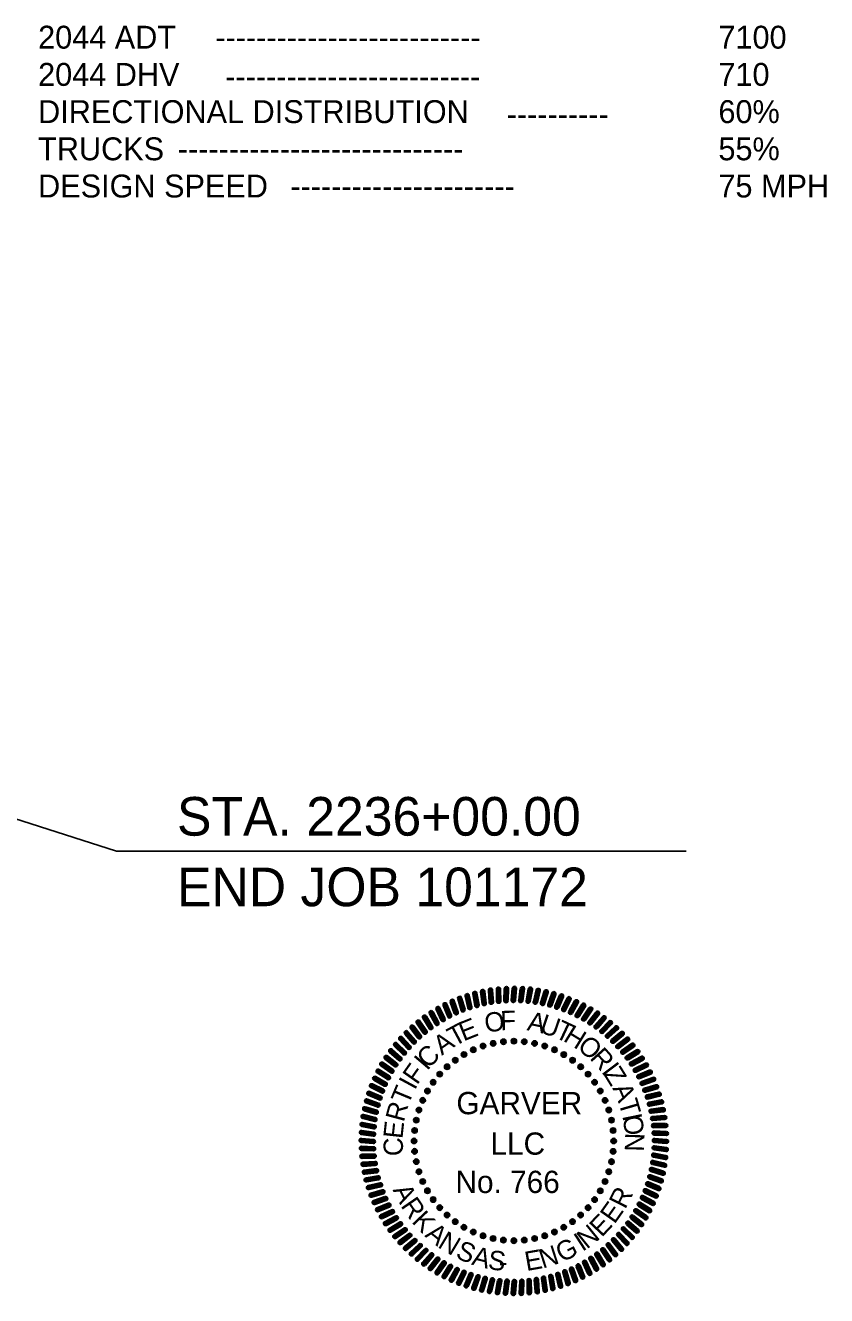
# Model space of a CAD drawing. Extents: x 1164457 to 1439835, y 1590918 to 1773502.
# Drawn here: x 1368755 to 1424710, y 1592326 to 1681073 of the extents above; entities that cross this region are included whole.
import ezdxf

# ---------------------------------------------------------------- set-up
doc = ezdxf.new("R2010")
doc.units = 0
for name, color, linetype in [('G-ANNO-STMP', 7, 'Continuous'), ('G-ANNO-TEXT', 7, 'Continuous'), ('R_Draft', 7, 'Continuous')]:
    doc.layers.add(name, color=color, linetype=linetype)

# ---------------------------------------------------------------- blocks, each defined once
blk = doc.blocks.new('SEALDO')
at = {"layer": 'G-ANNO-TEXT'}
for radius in [0.0396, 0.0305, 0.0213, 0.0122, 0.00305]:
    blk.add_circle((1.403, -0.456), radius, dxfattribs=at)
blk = doc.blocks.new('SEALRI')
at = {"layer": 'G-ANNO-TEXT'}
for p, q in [((-0.023, 2.258), (-0.038, 2.081)), ((-0.008, 2.281), (-0.028, 2.056)), ((0.004, 2.286), (-0.016, 2.049)), ((0.016, 2.285), (-0.004, 2.048)), ((0.028, 2.278), (0.008, 2.052)), ((0.023, 2.076), (0.038, 2.253))]:
    blk.add_line(p, q, dxfattribs=at)
for centre, start, end in [((0.008, 2.256), 355, 175), ((-0.008, 2.078), 175, 355)]:
    blk.add_arc(centre, 0.0305, start, end, dxfattribs=at)

msp = doc.modelspace()

# ---------------------------------------------------------------- linework, layer by layer
at = {"layer": 'R_Draft'}
for p, q in [((1375114, 1623387), (1297809, 1647974)), ((1414895, 1623387), (1375114, 1623387))]:
    msp.add_line(p, q, dxfattribs=at)

# ---------------------------------------------------------------- block references
at = {"layer": 'G-ANNO-STMP'}
for name, xscale, yscale, rotation in [('SEALRI', 4724.3165369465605, 4724.3165369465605, 18), ('SEALRI', 4724.31653694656, 4724.3165369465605, 15.000000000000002), ('SEALRI', 4724.31653694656, 4724.316536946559, 12.000000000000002), ('SEALRI', 4724.31653694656, 4724.31653694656, 9), ('SEALRI', 4724.316536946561, 4724.316536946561, 5.999999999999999), ('SEALRI', 4724.316536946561, 4724.3165369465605, 3), ('SEALRI', 4724.316536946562, 4724.316536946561, -2.9999999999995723), ('SEALRI', 4724.3165369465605, 4724.316536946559, -5.9999999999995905), ('SEALRI', 4724.316536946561, 4724.316536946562, -8.999999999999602), ('SEALRI', 4724.31653694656, 4724.316536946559, -11.999999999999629), ('SEALRI', 4724.3165369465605, 4724.316536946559, -14.999999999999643), ('SEALRI', 4724.3165369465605, 4724.316536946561, -17.99999999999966), ('SEALRI', 4724.3165369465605, 4724.316536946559, 30.000000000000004), ('SEALRI', 4724.316536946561, 4724.31653694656, 26.99999999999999), ('SEALRI', 4724.3165369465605, 4724.316536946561, 23.99999999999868), ('SEALRI', 4724.3165369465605, 4724.31653694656, 20.999999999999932), ('SEALRI', 4724.3165369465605, 4724.3165369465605, -20.99999999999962), ('SEALRI', 4724.3165369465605, 4724.31653694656, -23.999999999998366), ('SEALRI', 4724.316536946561, 4724.316536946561, -26.999999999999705), ('SEALRI', 4724.3165369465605, 4724.31653694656, -29.99999999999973), ('SEALRI', 4724.31653694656, 4724.31653694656, 36.00000000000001), ('SEALRI', 4724.3165369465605, 4724.31653694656, 33), ('SEALRI', 4724.3165369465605, 4724.3165369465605, -32.999999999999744), ('SEALRI', 4724.3165369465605, 4724.316536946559, -35.999999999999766), ('SEALRI', 4724.3165369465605, 4724.316536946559, 44.999999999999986), ('SEALRI', 4724.3165369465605, 4724.316536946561, 41.999999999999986), ('SEALRI', 4724.3165369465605, 4724.316536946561, 38.999999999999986), ('SEALRI', 4724.3165369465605, 4724.316536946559, -38.999999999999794), ('SEALRI', 4724.31653694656, 4724.3165369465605, -41.99999999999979), ('SEALRI', 4724.3165369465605, 4724.3165369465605, -44.999999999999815), ('SEALRI', 4724.3165369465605, 4724.3165369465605, 50.99999999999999), ('SEALRI', 4724.316536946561, 4724.316536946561, 47.99999999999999), ('SEALDO', 4724.316536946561, 4724.316536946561, 125.99999999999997), ('SEALDO', 4724.31653694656, 4724.31653694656, 119.99999999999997), ('SEALDO', 4724.31653694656, 4724.316536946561, 113.99999999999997), ('SEALDO', 4724.3165369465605, 4724.3165369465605, 107.99999999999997), ('SEALDO', 4724.31653694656, 4724.3165369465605, 101.99999999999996), ('SEALDO', 4724.316536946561, 4724.316536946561, 95.99999999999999), ('SEALDO', 4724.3165369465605, 4724.3165369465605, 90), ('SEALRI', 4724.3165369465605, 4724.316536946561, -47.99999999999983), ('SEALRI', 4724.3165369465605, 4724.316536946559, -50.999999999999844), ('SEALRI', 4724.3165369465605, 4724.31653694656, 56.99999999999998), ('SEALRI', 4724.31653694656, 4724.31653694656, 54), ('SEALDO', 4724.31653694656, 4724.31653694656, 144), ('SEALDO', 4724.3165369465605, 4724.316536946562, 138), ('SEALDO', 4724.31653694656, 4724.316536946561, 131.99999999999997), ('SEALDO', 4724.316536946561, 4724.316536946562, 83.99999999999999), ('SEALDO', 4724.31653694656, 4724.31653694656, 77.99999999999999), ('SEALDO', 4724.3165369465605, 4724.3165369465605, 72), ('SEALRI', 4724.3165369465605, 4724.31653694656, -53.99999999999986), ('SEALRI', 4724.316536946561, 4724.316536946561, -56.999999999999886), ('SEALRI', 4724.31653694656, 4724.316536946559, 63), ('SEALRI', 4724.31653694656, 4724.31653694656, 59.999999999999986), ('SEALDO', 4724.3165369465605, 4724.31653694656, 150), ('SEALDO', 4724.3165369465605, 4724.316536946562, 66.00000000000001), ('SEALRI', 4724.31653694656, 4724.3165369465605, -59.99999999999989), ('SEALRI', 4724.316536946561, 4724.316536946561, -62.99999999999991), ('SEALRI', 4724.3165369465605, 4724.316536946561, 65.99999999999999), ('SEALDO', 4724.31653694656, 4724.31653694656, 162.00000000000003), ('SEALDO', 4724.3165369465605, 4724.316536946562, 156.00000000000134), ('SEALDO', 4724.3165369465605, 4724.31653694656, 60.00000000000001), ('SEALDO', 4724.31653694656, 4724.31653694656, 54), ('SEALRI', 4724.3165369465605, 4724.316536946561, -65.99999999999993), ('SEALRI', 4724.3165369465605, 4724.3165369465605, 72), ('SEALRI', 4724.316536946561, 4724.316536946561, 68.99999999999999), ('SEALDO', 4724.316536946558, 4724.3165369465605, 168.00000000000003), ('SEALDO', 4724.3165369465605, 4724.316536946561, 48.00000000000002), ('SEALRI', 4724.3165369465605, 4724.3165369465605, -68.99999999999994), ('SEALRI', 4724.3165369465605, 4724.3165369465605, -71.99999999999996), ('SEALRI', 4724.31653694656, 4724.316536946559, 78.00000000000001), ('SEALRI', 4724.31653694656, 4724.31653694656, 75.00000000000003), ('SEALDO', 4724.3165369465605, 4724.3165369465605, -179.99999999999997), ('SEALDO', 4724.316536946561, 4724.3165369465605, 174.00000000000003), ('SEALDO', 4724.316536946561, 4724.316536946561, 42.000000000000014), ('SEALDO', 4724.31653694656, 4724.31653694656, 36.00000000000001), ('SEALRI', 4724.3165369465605, 4724.3165369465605, -74.99999999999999), ('SEALRI', 4724.31653694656, 4724.316536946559, -78), ('SEALRI', 4724.31653694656, 4724.3165369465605, 81), ('SEALDO', 4724.316536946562, 4724.316536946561, -173.99999999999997), ('SEALDO', 4724.3165369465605, 4724.31653694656, 29.999999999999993), ('SEALRI', 4724.31653694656, 4724.31653694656, -81.00000000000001), ('SEALRI', 4724.3165369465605, 4724.316536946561, 87.00000000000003), ('SEALRI', 4724.316536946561, 4724.316536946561, 84.00000000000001), ('SEALDO', 4724.31653694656, 4724.316536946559, -167.99999999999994), ('SEALDO', 4724.3165369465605, 4724.316536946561, 23.99999999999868), ('SEALRI', 4724.316536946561, 4724.316536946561, -84.00000000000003), ('SEALRI', 4724.3165369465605, 4724.316536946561, -87.00000000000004), ('SEALRI', 4724.3165369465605, 4724.3165369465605, 90.00000000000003), ('SEALRI', 4724.316536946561, 4724.3165369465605, 93), ('SEALDO', 4724.3165369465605, 4724.316536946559, -161.9999999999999), ('SEALDO', 4724.3165369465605, 4724.3165369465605, 18), ('SEALRI', 4724.316536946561, 4724.316536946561, -93.00000000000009), ('SEALRI', 4724.3165369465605, 4724.3165369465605, -90.00000000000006), ('SEALRI', 4724.316536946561, 4724.316536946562, 96.00000000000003), ('SEALDO', 4724.31653694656, 4724.31653694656, -156.00000000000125), ('SEALDO', 4724.3165369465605, 4724.3165369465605, -149.99999999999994), ('SEALDO', 4724.316536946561, 4724.316536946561, 5.999999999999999), ('SEALDO', 4724.31653694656, 4724.316536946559, 12.000000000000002), ('SEALRI', 4724.3165369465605, 4724.3165369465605, -96.0000000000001), ('SEALRI', 4724.3165369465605, 4724.3165369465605, 99.00000000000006), ('SEALRI', 4724.31653694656, 4724.316536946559, 102.00000000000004), ('SEALDO', 4724.316536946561, 4724.316536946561, -143.99999999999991), ('SEALRI', 4724.31653694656, 4724.316536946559, -102.00000000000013), ('SEALRI', 4724.3165369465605, 4724.3165369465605, -99.00000000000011), ('SEALRI', 4724.3165369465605, 4724.3165369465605, 105.00000000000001), ('SEALRI', 4724.3165369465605, 4724.3165369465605, 108.00000000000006), ('SEALDO', 4724.316536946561, 4724.316536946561, -137.9999999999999), ('SEALDO', 4724.31653694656, 4724.3165369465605, -6.000000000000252), ('SEALRI', 4724.3165369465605, 4724.31653694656, -108.00000000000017), ('SEALRI', 4724.316536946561, 4724.31653694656, -105.00000000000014), ('SEALRI', 4724.31653694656, 4724.3165369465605, 111.00000000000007), ('SEALRI', 4724.3165369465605, 4724.3165369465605, 114.00000000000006), ('SEALDO', 4724.3165369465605, 4724.3165369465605, -131.99999999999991), ('SEALDO', 4724.316536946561, 4724.31653694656, -125.9999999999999), ('SEALDO', 4724.3165369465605, 4724.3165369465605, -18.000000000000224), ('SEALDO', 4724.31653694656, 4724.31653694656, -12.000000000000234), ('SEALRI', 4724.3165369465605, 4724.316536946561, -114.0000000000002), ('SEALRI', 4724.3165369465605, 4724.3165369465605, -111.00000000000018), ('SEALRI', 4724.31653694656, 4724.3165369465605, 117.00000000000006), ('SEALRI', 4724.31653694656, 4724.31653694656, 120.00000000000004), ('SEALDO', 4724.3165369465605, 4724.3165369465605, -119.99999999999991), ('SEALDO', 4724.3165369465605, 4724.316536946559, -23.999999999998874), ('SEALRI', 4724.3165369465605, 4724.316536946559, -120.00000000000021), ('SEALRI', 4724.31653694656, 4724.316536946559, -117.00000000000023), ('SEALRI', 4724.31653694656, 4724.31653694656, 123.00000000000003), ('SEALRI', 4724.316536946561, 4724.31653694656, 126.00000000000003), ('SEALDO', 4724.316536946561, 4724.316536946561, -113.99999999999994), ('SEALDO', 4724.3165369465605, 4724.31653694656, -107.99999999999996), ('SEALDO', 4724.3165369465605, 4724.3165369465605, -36.00000000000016), ('SEALDO', 4724.31653694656, 4724.3165369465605, -30.00000000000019), ('SEALRI', 4724.3165369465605, 4724.3165369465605, -126.00000000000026), ('SEALRI', 4724.3165369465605, 4724.3165369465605, -123.00000000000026), ('SEALRI', 4724.3165369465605, 4724.3165369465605, 129.00000000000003), ('SEALRI', 4724.3165369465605, 4724.31653694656, 132), ('SEALDO', 4724.31653694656, 4724.316536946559, -101.99999999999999), ('SEALDO', 4724.316536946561, 4724.316536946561, -96), ('SEALDO', 4724.3165369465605, 4724.3165369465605, -90.00000000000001), ('SEALDO', 4724.3165369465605, 4724.3165369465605, -60.0000000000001), ('SEALDO', 4724.3165369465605, 4724.3165369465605, -54.000000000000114), ('SEALDO', 4724.3165369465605, 4724.3165369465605, -48.00000000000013), ('SEALDO', 4724.31653694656, 4724.31653694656, -42.00000000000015), ('SEALRI', 4724.31653694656, 4724.31653694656, -132.00000000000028), ('SEALRI', 4724.3165369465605, 4724.31653694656, -129.00000000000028), ('SEALRI', 4724.31653694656, 4724.316536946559, 135), ('SEALRI', 4724.3165369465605, 4724.316536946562, 138), ('SEALRI', 4724.31653694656, 4724.31653694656, 140.99999999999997), ('SEALDO', 4724.316536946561, 4724.316536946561, -84.00000000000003), ('SEALDO', 4724.31653694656, 4724.3165369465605, -78.00000000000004), ('SEALDO', 4724.3165369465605, 4724.316536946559, -72.00000000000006), ('SEALDO', 4724.3165369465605, 4724.3165369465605, -66.00000000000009), ('SEALRI', 4724.3165369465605, 4724.316536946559, -141.0000000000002), ('SEALRI', 4724.3165369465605, 4724.31653694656, -138.00000000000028), ('SEALRI', 4724.31653694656, 4724.31653694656, -135.00000000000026), ('SEALRI', 4724.31653694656, 4724.31653694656, 144), ('SEALRI', 4724.31653694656, 4724.3165369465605, 146.99999999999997), ('SEALRI', 4724.3165369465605, 4724.3165369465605, 149.99999999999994), ('SEALRI', 4724.3165369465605, 4724.3165369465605, -150.00000000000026), ('SEALRI', 4724.3165369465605, 4724.3165369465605, -147.00000000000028), ('SEALRI', 4724.31653694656, 4724.3165369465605, -144.00000000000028), ('SEALRI', 4724.3165369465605, 4724.3165369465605, 152.99999999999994), ('SEALRI', 4724.31653694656, 4724.316536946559, 156.00000000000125), ('SEALRI', 4724.3165369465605, 4724.3165369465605, 159), ('SEALRI', 4724.31653694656, 4724.31653694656, 161.99999999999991), ('SEALRI', 4724.31653694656, 4724.3165369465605, -162.00000000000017), ('SEALRI', 4724.3165369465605, 4724.3165369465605, -159.00000000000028), ('SEALRI', 4724.316536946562, 4724.316536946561, -156.00000000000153), ('SEALRI', 4724.31653694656, 4724.316536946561, -153.00000000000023), ('SEALRI', 4724.31653694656, 4724.3165369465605, 164.99999999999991), ('SEALRI', 4724.31653694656, 4724.316536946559, 167.99999999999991), ('SEALRI', 4724.3165369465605, 4724.3165369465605, 170.9999999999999), ('SEALRI', 4724.3165369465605, 4724.316536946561, 173.9999999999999), ('SEALRI', 4724.316536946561, 4724.316536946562, 176.9999999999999), ('SEALRI', 4724.3165369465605, 4724.3165369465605, 179.99999999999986), ('SEALRI', 4724.316536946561, 4724.316536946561, -177.00000000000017), ('SEALRI', 4724.3165369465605, 4724.31653694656, -174.00000000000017), ('SEALRI', 4724.3165369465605, 4724.3165369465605, -171.00000000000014), ('SEALRI', 4724.31653694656, 4724.3165369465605, -168.0000000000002), ('SEALRI', 4724.3165369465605, 4724.316536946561, -165.0000000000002)]:
    msp.add_blockref(name, (1402870, 1603133), dxfattribs=dict(at, xscale=xscale, yscale=yscale, rotation=rotation))
at = {"layer": 'G-ANNO-STMP', "xscale": 4724.3165369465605, "yscale": 4724.3165369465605}
for name in ['SEALRI', 'SEALDO']:
    msp.add_blockref(name, (1402870, 1603133), dxfattribs=at)

# ---------------------------------------------------------------- texts
at = {"layer": 'G-ANNO-STMP'}
for s, rotation, p in [('E', 21.61044, (1399351, 1610080)), ('O', 8.2771, (1400914, 1610689)), ('F', 1.61044, (1401938, 1610864)), ('A', 348.2771, (1403742, 1610876)), ('U', 341.27715, (1404586, 1610741)), ('T', 28.2771, (1398698, 1609699)), ('T', 334.94377, (1405647, 1610398)), ('H', 328.2771, (1406255, 1610158)), ('A', 34.94377, (1397840, 1609077)), ('O', 319.7874, (1407231, 1609604)), ('I', 49.74076, (1396814, 1607988)), ('C', 44.38813, (1396883, 1608126)), ('R', 311.99331, (1408116, 1608897)), ('F', 54.94377, (1396111, 1606999)), ('I', 307.00814, (1408940, 1607971)), ('Z', 301.61044, (1409099, 1607809)), ('I', 61.61044, (1395950, 1606634)), ('T', 67.43139, (1395497, 1605588)), ('A', 292.97516, (1409735, 1606828)), ('R', 74.94377, (1395181, 1604399)), ('T', 286.3085, (1410158, 1605851)), ('I', 281.61044, (1410429, 1604901)), ('O', 276.48226, (1410481, 1604853)), ('E', 83.89849, (1395084, 1603245)), ('C', 91.88416, (1395144, 1602092)), ('N', 268.2771, (1410650, 1603714)), ('A', 296.57465, (1394394, 1599713)), ('R', 304.61826, (1394927, 1598601)), ('R', 63.09594, (1410647, 1598312)), ('E', 54.73091, (1409896, 1597276)), ('K', 313.3805, (1395685, 1597472)), ('E', 46.68075, (1409002, 1596354)), ('A', 321.25836, (1396598, 1596485)), ('N', 329.10994, (1397486, 1595738)), ('I', 32.97899, (1407646, 1595369)), ('N', 38.98211, (1407959, 1595529)), ('S', 337.62936, (1398732, 1594979)), ('A', 345.40726, (1399868, 1594502)), ('N', 17.86862, (1404883, 1594203)), ('G', 26.41319, (1406213, 1594616)), ('S', 352.80457, (1401013, 1594180)), ('E', 10.06947, (1403753, 1594036)), ('-', 0.83848, (1401828, 1594004))]:
    msp.add_text(s, height=1350, rotation=rotation, dxfattribs=at).set_placement(p)
for s, p in [('GARVER', (1398857, 1604998)), ('LLC', (1401235, 1602169)), ('No. 766', (1398790, 1599494))]:
    msp.add_text(s, height=1555.1, dxfattribs=at).set_placement(p)
at = {"layer": 'R_Draft'}
for s, height, p in [('2044 ADT', 1600, (1369642, 1679449)), ('7100', 1600, (1417156, 1679449)), ('--------------------------', 1600, (1382019, 1679449)), ('2044 DHV', 1600, (1369642, 1676849)), ('710', 1600, (1417156, 1676849)), ('-------------------------', 1600, (1382713, 1676716)), ('DIRECTIONAL DISTRIBUTION', 1600, (1369642, 1674249)), ('60%', 1600, (1417156, 1674249)), ('----------', 1600, (1402367, 1674071)), ('TRUCKS', 1600, (1369642, 1671649)), ('55%', 1600, (1417156, 1671649)), ('----------------------------', 1600, (1379398, 1671649)), ('DESIGN SPEED', 1600, (1369642, 1669050)), ('75 MPH', 1600, (1417156, 1669050)), ('----------------------', 1600, (1387259, 1669050)), ('STA. 2236+00.00', 2700, (1379340, 1624462)), ('END JOB 101172', 2700, (1379340, 1619532))]:
    msp.add_text(s, height=height, dxfattribs=at).set_placement(p)

doc.saveas('drawing.dxf')
